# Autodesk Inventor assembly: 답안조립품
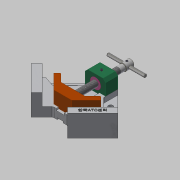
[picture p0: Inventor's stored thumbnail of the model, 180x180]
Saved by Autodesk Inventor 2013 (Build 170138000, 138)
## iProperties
Created: 2019-04
Part Number: 답안조립품
Document SubType Name: Assembly
Designer: Administrator
Author: Administrator
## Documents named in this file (11)
- C:\Users\Administrator\Desktop\490407V1026\답안조립품.iam
- C:\Users\Administrator\Desktop\490407V1026\베이스.ipt
- C:\Users\Administrator\Desktop\490407V1026\리드스크류.ipt
- C:\Users\Administrator\Desktop\490407V1026\멈춤나사 M4x5.ipt
- C:\Users\Administrator\Desktop\490407V1026\멈춤나사 M4x10.ipt
- C:\Users\Administrator\Desktop\490407V1026\볼트 M4x16.ipt
- C:\Users\Administrator\Desktop\490407V1026\부시.ipt
- C:\Users\Administrator\Desktop\490407V1026\서포트.ipt
- C:\Users\Administrator\Desktop\490407V1026\조.ipt
- C:\Users\Administrator\Desktop\490407V1026\평행 핀 2.5x24.ipt
- C:\Users\Administrator\Desktop\490407V1026\핸들.ipt
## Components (1 placed, 1 different names)
1. 핸들:1 — 각도:1
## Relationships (1: Angle 1)
- 각도:1 [Angle]: 핸들:1
